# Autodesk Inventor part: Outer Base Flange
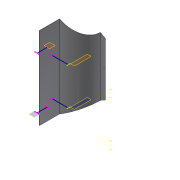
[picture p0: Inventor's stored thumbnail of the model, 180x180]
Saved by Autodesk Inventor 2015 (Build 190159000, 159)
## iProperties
Created: 2013-06
Part Number: Outer Base Flange
Material: Steel, Mild
Document SubType Name: Sheet Metal
Designer: 1103005
Density: 7.86 g/cm^3
Sheet Metal Rule: Default_mm
Appearance: Steel
Flat Pattern Width: 27.9338 cm
Flat Pattern Length: 40.4145 cm
Flat Pattern Area: 1128.93 cm^2
Sheet Metal Width: 279.338 mm
Sheet Metal Length: 404.145 mm
Sheet Metal Area: 112893.248 mm^2
Author: 1103005
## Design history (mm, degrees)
node "Contour Flange1"
  sketch "Sketch1"
    geometry: L1 (-225, 200)-(-250, 200); L2 (-350, 100)-(-350, 0); A1 r 100 centre (-350, 200) between (-350, 100) and (-250, 200); 1 further point
    constraints: 4 end point, 2 horizontal alignment, 2 point on circle, 1 centre point, 1 horizontal, 1 perpendicular
    dimensions: "d0" = 100 radius of A1; "d3" = 200 distance from line of point (0, 0) L1; "d4" = 250 horizontal distance of point (0, 0) L1.end; "d5" = 25 distance of L1.start L1.end; "d20" = 100 distance of L2.end L2.start
sketch "Sketch2"
  geometry: L1 (225, 538.675)-(475, 394.338); L2 (475, 394.338)-(475, 105.662); L3 (475, 105.662)-(225, -38.675); L4 (225, -38.675)-(-25, 105.662); L5 (-25, 105.662)-(-25, 394.338); L6 (225, 250)-(-25, 394.338); L7 (-225.333, 510)-(-25, 394.338); L8 (-225.333, 510)-(114.711, 510); L9 (114.711, 510)-(225, 538.675); L10 (225, 250)-(225, 538.675); 1 further point
  constraints: 20 end point, 2 perpendicular, 1 coincident, 1 collinear, 1 parallel, 1 vertical, 11 other
  dimensions: "d16" = 500 distance between parallel lines of L2 L5; "d17" = 260 distance from line of point (225, 250) L8
cut "Cut1" sketch "Sketch2" dims "d18" = 1 (= Thickness), "d19" = 0
mirror "Mirror1"
workplane "Work Plane1"
sketch "Sketch3"
  geometry: L1 (82, 105.2)-(82, 122.2) reference; L2 (4, 105.2)-(4, 122.2) reference; L3 (4, 113.7)-(82, 113.7); 1 further point
  constraints: 2 end point, 2 midpoint
  node "Reference1"
  node "Reference2"
workplane "Work Plane2"
sketch "Sketch4"
  geometry: L1 (-21, 105.2)-(-21, 122.2) reference; L2 (-99, 105.2)-(-99, 122.2) reference; L3 (-21, 113.7)-(-99, 113.7); 1 further point
  constraints: 2 end point, 2 midpoint
  node "Reference3"
  node "Reference4"
workplane "Work Plane3"
sketch "Sketch5"
  geometry: L1 (8.5, -12.5)-(-8.5, -12.5) reference; L2 (-8.5, -62.5)-(8.5, -62.5) reference; L3 (0, -12.5)-(0, -62.5); 1 further point
  constraints: 2 end point, 2 midpoint
  node "Reference5"
  node "Reference6"
workplane "Work Plane4"
sketch "Sketch6"
  geometry: L1 (-8.5, 62.5)-(8.5, 62.5) reference; L2 (8.5, 12.5)-(-8.5, 12.5) reference; L3 (0, 12.5)-(0, 62.5); 1 further point
  constraints: 2 end point, 2 midpoint
  node "Reference7"
  node "Reference8"
sketch "Sketch7"
  geometry: L1 (0, 0)-(23.02, 13.29) reference; L2 (23.02, 273.098)-(23.02, 13.29) reference; L3 (23.02, 273.098)-(0, 286.388) reference; L4 (0, 286.388)-(0, 0) reference; 1 further point
node "A-Side Definition"
node "Hole1"
node "Hole4"
node "Hole6"
body "Solid1"
face "Plate1" dims "d6" = 1 (= BendReliefWidth), "d7" = 0.5 (= BendReliefDepth), "d8" = 2 (= MinimumRemnant), "d9" = 1 (= BendRadius), "d10" = 500, "d11" = 1 (= BendRadius), "d12" = 1.2, "d13" = 4 (= CornerReliefSize), "d14" = 1 (= GapSize), "d15" = 1 (= JacobiRadiusSize), "SeamGap" = 0.01, "Thickness" = 1
bend "Bend1" dims "d6" = 1 (= BendReliefWidth), "d7" = 0.5 (= BendReliefDepth), "d8" = 2 (= MinimumRemnant), "d9" = 1 (= BendRadius), "d11" = 1 (= BendRadius), "d12" = 1.2, "SeamGap" = 0.01, "Thickness" = 1
feature "Corner1" dims "d12" = 1.2, "d13" = 4 (= CornerReliefSize), "d14" = 1 (= GapSize), "d15" = 1 (= JacobiRadiusSize)
sketch "Sketch9"
  geometry: 3 further points
hole "Hole2" sketch "Sketch9" diameter "d28" = 5.5; stored, may be unused: countersink angle "d32" = 90 deg, drill point angle "d34" = 0 deg; dims "d29" = 6, "d30" = 4, "d31" = 2, "d33" = 8
sketch "Sketch10"
  geometry: 3 further points
hole "Hole3" sketch "Sketch10" diameter "d35" = 5.5; stored, may be unused: countersink angle "d39" = 90 deg, drill point angle "d41" = 0 deg; dims "d36" = 6, "d37" = 4, "d38" = 2, "d40" = 8
sketch "Sketch11"
  geometry: 3 further points
hole "Hole5" sketch "Sketch11" diameter "d42" = 5.5; stored, may be unused: countersink angle "d46" = 90 deg, drill point angle "d48" = 0 deg; dims "d43" = 6, "d44" = 4, "d45" = 2, "d47" = 8
feature "Definition1"
other parameters: "BendRadius" = 1 (= Thickness), "BendReliefWidth" = 1 (= Thickness), "BendReliefDepth" = 0.5 (= 0.5 x Thickness), "CornerReliefSize" = 4 (= 4 x Thickness), "MinimumRemnant" = 2 (= 2 x Thickness), "TransitionRadius" = 1 (= BendRadius), "JacobiRadiusSize" = 1 (= BendRadius), "GapSize" = 1 (= Thickness), "BendRadius" = 1, "BendReliefDepth" = 0.5, "BendReliefWidth" = 1, "CornerReliefSize" = 4, "GapSize" = 1, "JacobiRadiusSize" = 1, "MinimumRemnant" = 2, "Thickness" = 1, "TransitionRadius" = 1
